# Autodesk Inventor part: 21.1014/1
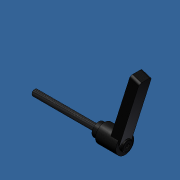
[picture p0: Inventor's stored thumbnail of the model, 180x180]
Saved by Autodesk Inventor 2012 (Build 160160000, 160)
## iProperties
Created: 2007-06
Part Number: 21.1014/1
Document SubType Name: Modeling
Designer: Andy Moles
Material: Steel
Mass: 126.061 g
Surface Area: 61.1606 cm^2
Volume: 16.0587 cm^3
Density: 7.85 g/cm^3
Description: SLIDE LOCK WITH M6X65 STUD
Vendor: S
Author: Andy Moles
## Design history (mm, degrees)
feature "Base1"
sketch "Sketch1"
  geometry: C1 r 6.731 at (0, 0) reference; C2 r 3 at (0, 0)
  constraints: 1 centre point, 1 coincident
  dimensions: "d0" = 6 diameter of C2
extrude "Extrusion1" join sketch "Sketch1" distance "d1" = 65; taper "d2" = 0 deg
thread "Thread1" dims "d3" = 10, "d4" = 0
chamfer "Chamfer1" distance "d5" = 0.5; stored, may be unused: second distance "d6" = 2, angle "d7" = 45 deg
sketch "Sketch2"
  geometry: C1 r 6.731 at (6.35, -2.662) reference; C2 r 5.5 at (6.35, -2.662)
  constraints: 1 centre point, 1 concentric
  dimensions: "d8" = 11 diameter of C2
extrude "Extrusion2" cut sketch "Sketch2" distance "d9" = 10; taper "d10" = 0 deg
sketch "Sketch3"
  geometry: C1 r 5.5 at (6.35, -2.662); A1 r 5.5 centre (6.35, -2.662) between (11.813, -2.022) and (0.887, -2.022) reference; A2 r 9.169 centre (6.35, -2.662) between (0, 3.952) and (12.7, 3.952) reference
  constraints: 1 centre point, 1 coincident, 1 concentric
extrude "Extrusion3" join sketch "Sketch3" distance "d11" = 3; taper "d12" = 0 deg
fillet "Fillet1" dims "d13" = 1
sketch "Sketch4"
  geometry: L1 (-1.155, 2)-(1.155, 2); L2 (1.155, 2)-(2.309, 0); L3 (2.309, 0)-(1.155, -2); L4 (1.155, -2)-(-1.155, -2); L5 (-1.155, -2)-(-2.309, 0); L6 (-2.309, 0)-(-1.155, 2); C1 r 4.5 at (0, 0) reference; 2 further points
  constraints: 12 end point, 4 equal length, 4 vertical alignment, 2 midpoint, 2 parallel, 1 horizontal, 1 horizontal alignment
  dimensions: "d15" = 120 deg angle of L3 L2; "d16" = 120 deg angle of L1 L6 (derived); "d17" = 4 distance between parallel lines of L4 L1
extrude "Extrusion4" cut sketch "Sketch4" distance "d18" = 2; taper "d19" = 0 deg
body "Solid1"
other parameters: "STUD_LENGTH" = 65 [user parameter]
